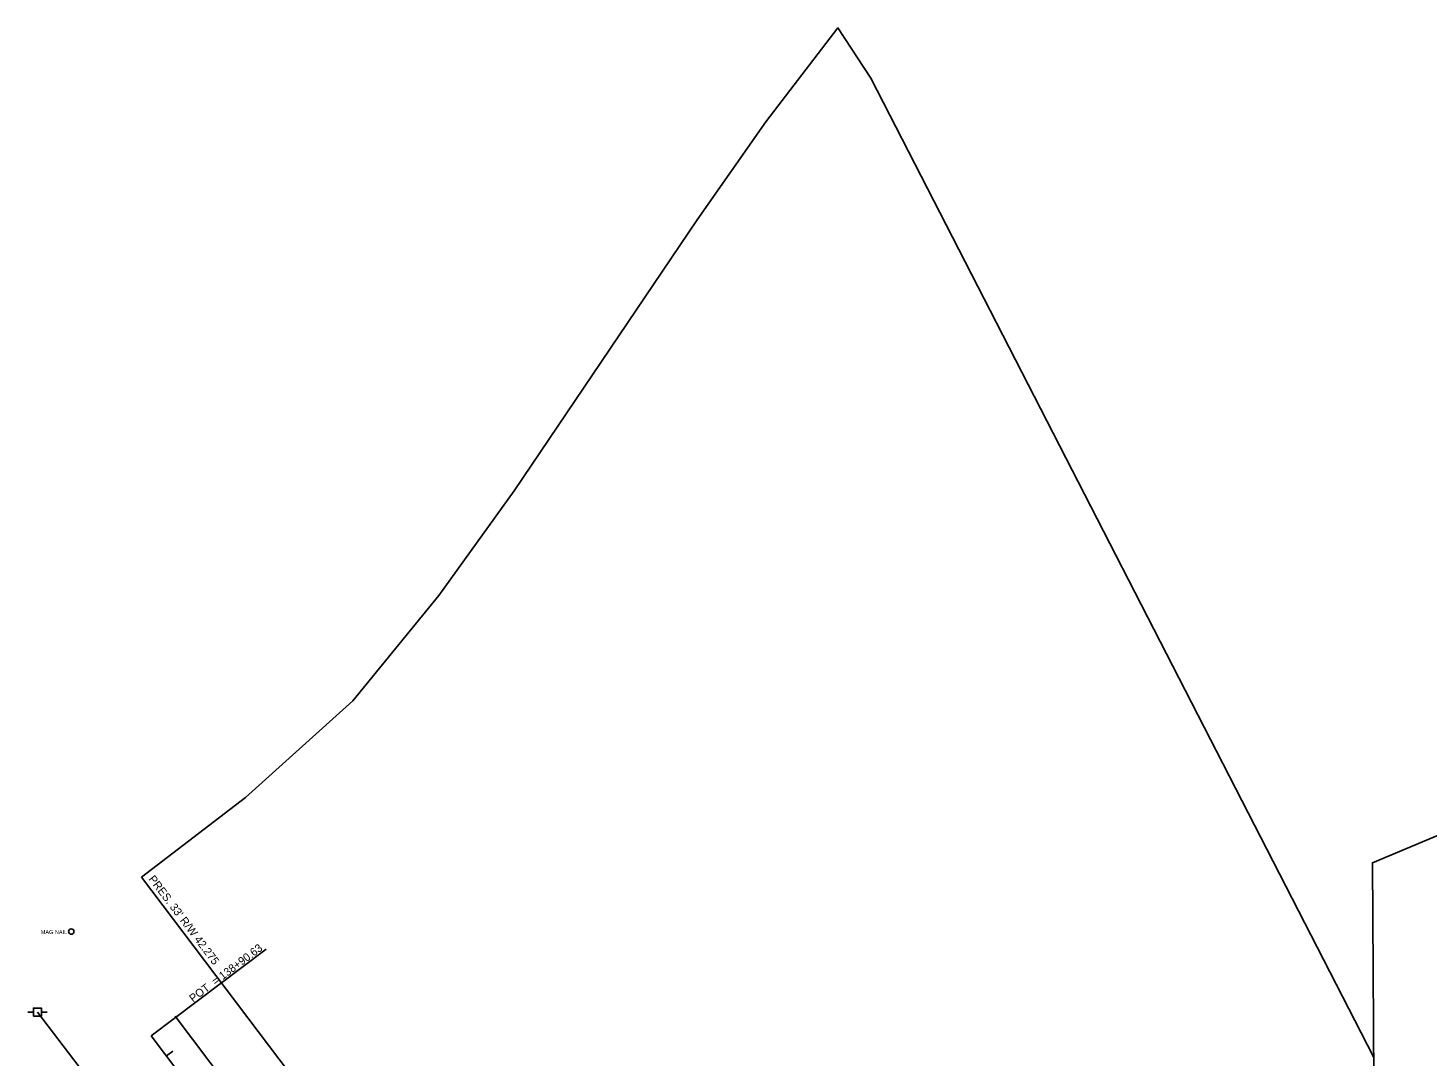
# Model space of a CAD drawing. Extents: x 1642870 to 1644553, y 1183846 to 1185844.
# Drawn here: x 1643183 to 1643707, y 1185458 to 1185844 of the extents above; entities that cross this region are included whole.
import ezdxf

# ---------------------------------------------------------------- set-up
doc = ezdxf.new("R2010")
doc.units = 0
for name, color, linetype in [('RD_EX_DV_Prop', 7, 'Continuous'), ('RD_EX_DV_Prop_txCode', 7, 'Continuous'), ('RD_EX_DV_PropPin', 7, 'Continuous'), ('RD_EX_Road', 7, 'Continuous'), ('RD_EX_RW', 7, 'Continuous'), ('RD_EX_RW_TX', 7, 'Continuous'), ('RD_EX_UT', 7, 'Continuous'), ('RD_HC_Cl', 7, 'Continuous'), ('RD_HC_Data', 7, 'Continuous'), ('RD_HC_Data_Tic', 7, 'Continuous')]:
    doc.layers.add(name, color=color, linetype=linetype)

msp = doc.modelspace()

# ---------------------------------------------------------------- linework, layer by layer
at = {"layer": 'RD_EX_DV_Prop'}
for points in [[(1643225.58, 1185525.32), (1643264.53, 1185555.2), (1643304.79, 1185591.4), (1643337.01, 1185630.92), (1643365.23, 1185670.13), (1643433.85, 1185771.76), (1643459.58, 1185808.53), (1643486.6, 1185843.69), (1643498.93, 1185824.91), (1643687.38, 1185457.7)], [(1643555.23, 1185089.37), (1643688.83, 1185225.87), (1643686.92, 1185530.7), (1643871.11, 1185608.06), (1644161.63, 1185636.32)]]:
    msp.add_lwpolyline(points, dxfattribs=at)
at = {"layer": 'RD_EX_DV_PropPin'}
msp.add_circle((1643199.23, 1185504.92), 1, dxfattribs=at)
at = {"layer": 'RD_EX_Road'}
msp.add_lwpolyline([(1643716.57, 1184841.11), (1643687.94, 1184878.71), (1643661.63, 1184911.52), (1643633.08, 1184951.12), (1643634.45, 1184955.59), (1643609.05, 1184988.1), (1643606.52, 1184986.89), (1643574.96, 1185026.91), (1643564.6, 1185041.88), (1643550.54, 1185060.85), (1643540.04, 1185074.69), (1643512.74, 1185111.37), (1643480.98, 1185151.22), (1643451.76, 1185190.72), (1643421.5, 1185230.93), (1643390.17, 1185273.24), (1643364.37, 1185306.43), (1643334.06, 1185346.62), (1643327.33, 1185356.11), (1643302.33, 1185388.39), (1643271.08, 1185429.6), (1643238.22, 1185473.19)], dxfattribs=at)
at = {"layer": 'RD_EX_RW'}
msp.add_line((1643225.58, 1185525.31), (1644072.06, 1184405.88), dxfattribs=at)
at = {"layer": 'RD_EX_UT'}
for p, q in [((1643183, 1185474.7), (1643185.06, 1185474.7)), ((1643186.56, 1185474.73), (1643186.56, 1185474.73)), ((1643188.06, 1185474.7), (1643190.2, 1185474.7))]:
    msp.add_line(p, q, dxfattribs=at)
msp.add_lwpolyline([(1643185.06, 1185473.23), (1643185.06, 1185476.23), (1643188.06, 1185476.23), (1643188.06, 1185473.23)], close=True, dxfattribs=at)
msp.add_lwpolyline([(1643186.56, 1185474.73), (1643287.54, 1185342.18), (1643364.99, 1185240.63), (1643453.31, 1185123.93), (1643542.71, 1185007.25), (1643592.86, 1185049.73)], dxfattribs=at)
at = {"layer": 'RD_HC_Cl'}
msp.add_line((1643229.22, 1185465.79), (1644045.74, 1184385.98), dxfattribs=at)
at = {"layer": 'RD_HC_Data'}
msp.add_line((1643229.22, 1185465.79), (1643272.23, 1185498.31), dxfattribs=at)
at = {"layer": 'RD_HC_Data_Tic'}
msp.add_line((1643234.87, 1185458.32), (1643237.26, 1185460.12), dxfattribs=at)

# ---------------------------------------------------------------- texts
at = {"layer": 'RD_EX_DV_Prop_txCode'}
msp.add_text('MAG NAIL', height=1.5, dxfattribs=at).set_placement((1643187.8, 1185503.97))
at = {"layer": 'RD_EX_RW_TX'}
msp.add_text("PRES. 33' R/W 42.275", height=3, rotation=307.0956, dxfattribs=at).set_placement((1643228.02, 1185524.57))
at = {"layer": 'RD_HC_Data'}
msp.add_text('POT  = 138+90.63', height=3, rotation=37.0956, dxfattribs=at).set_placement((1643244.87, 1185478.25))

doc.saveas('drawing.dxf')
